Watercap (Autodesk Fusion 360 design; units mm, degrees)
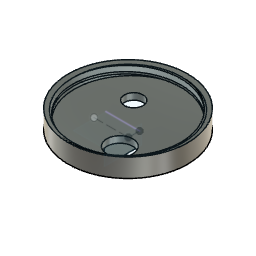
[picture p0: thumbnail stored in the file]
cylinder_primitive "CylinderPrimitive1" Height 10 Diameter 64
shell "Shell1" innerThickness 3.5
thread "Thread1"
hole "Hole1" HoleDepth 30 HoleDiameter 14 TipAngle 118
hole "Hole2" HoleDepth 30 HoleDiameter 10 TipAngle 118
box_primitive "BoxPrimitive1" DistanceX 20 DistanceY 20 DistanceZ 10 OffsetDistanceX 0 OffsetDistanceY 0
move "Move1"
sketch "Sketch5" plane through (0, 0, -9.5813) normal (0, 0, -1) x axis (1, 0, 0)
  line L1 (-18.8277, 13.8567) -> (1.1723, 13.8567)
  line L2 (-18.8277, -6.1433) -> (-18.8277, 13.8567)
  line L3 (1.1723, -6.1433) -> (-18.8277, -6.1433)
  line L4 (1.1723, 13.8567) -> (1.1723, -6.1433)
  line L5 (0.0733, 11.5199) -> (-17.9267, 11.5199)
  line L6 (0.0733, -6.4801) -> (0.0733, 11.5199)
  line L7 (-17.9267, -6.4801) -> (0.0733, -6.4801)
  line L8 (-17.9267, 11.5199) -> (-17.9267, -6.4801)
  point P6 (-17.9267, 11.5199)
  point P7 (0.0733, 11.5199)
  point P9 (-17.9267, -6.4801)
  horizontal L5
  vertical L6
  horizontal L7
  vertical L8
  dimension "d15" distance P6 P7 = 18
  dimension "d16" distance P6 P9 = 18
extrude "Extrude1" cut sketch "Sketch5" profile of L3 L5 L6 L8 against normal blind 6
sketch "Sketch6" plane through (0, 0, -3.5813) normal (0, 0, -1) x axis (1, 0, 0)
  line L1 (-17.9267, -6.1433) -> (-17.9267, 11.5199)
  line L2 (0.0733, 11.5199) -> (0.0733, -6.1433)
  line L3 (-17.9267, 11.5199) -> (0.0733, 11.5199)
  line L4 (-15.9267, -6.1433) -> (-17.9267, -6.1433)
  line L5 (-15.9267, -4.1433) -> (-15.9267, -6.1433)
  line L6 (-17.9267, -4.1433) -> (-15.9267, -4.1433)
  line L7 (-17.9267, -6.1433) -> (-17.9267, -4.1433)
  line L8 (0.0733, -6.1433) -> (-17.9267, -6.1433)
  point P3 (-17.9267, -6.1433)
  point P6 (-17.9267, -6.1433)
  point P7 (-15.9267, -6.1433)
  point P9 (-17.9267, -4.1433)
  horizontal L4
  vertical L5
  horizontal L6
  vertical L7
  coincident P3 P6
  dimension "d19" distance P6 P7 = 2
  dimension "d20" distance P6 P9 = 2
extrude "Extrude2" new body sketch "Sketch6" profile of L1 L4 L5 L6 L7 along normal blind 6
rectangular_pattern "R-Pattern1" uSpaceDistance -16 vSpaceDistance 9
sketch "Sketch7" plane through (1.1723, 0, 0) normal (1, 0, 0) x axis (0, 1, 0)
  line L1 (6.1433, 0.4187) -> (6.1433, -9.5813)
  line L2 (-13.8567, 0.4187) -> (6.1433, 0.4187)
  line L3 (-13.8567, -9.5813) -> (-13.8567, 0.4187)
  line L4 (6.1433, -9.5813) -> (-13.8567, -9.5813)
sketch "Sketch8" plane through (0, 0, -3.5813) normal (0, 0, -1) x axis (1, 0, 0)
  line L1 (-17.9267, -6.1433) -> (-17.9267, 11.5199)
  line L2 (0.0733, 11.5199) -> (0.0733, -6.1433)
  line L3 (-17.9267, 11.5199) -> (0.0733, 11.5199)
  line L4 (0.0733, -0.1433) -> (0.0733, -6.1433)
  line L5 (-18.3663, -0.1433) -> (0.0733, -0.1433)
  line L6 (0.0733, -6.1433) -> (-17.9267, -6.1433)
  point P4 (0.0733, -6.1433)
  point P6 (0.0733, -6.1433)
  point P7 (0.0733, -0.1433)
  coincident P4 P6
  coincident L2 P7
  perpendicular L2 L5
  dimension "d27" distance P6 P7 = 6
hole "Hole3" HoleDepth 5 HoleDiameter 2 TipAngle 118
rectangular_pattern "R-Pattern2" uSpaceDistance 14 vSpaceDistance 0
sketch "Sketch10" plane through (0, 0, -9.5813) normal (0, 0, -1) x axis (1, 0, 0)
  line L1 (-14, 11.2881) -> (-4.8967, 11.2881)
  line L2 (-14, 14) -> (-14, 11.2881)
  line L3 (-4.8967, 14) -> (-14, 14)
  line L4 (-4.8967, 11.2881) -> (-4.8967, 14)
  horizontal L1
  vertical L2
  horizontal L3
  vertical L4
extrude "Extrude3" cut sketch "Sketch10" against normal blind 4
combine "Combine1"
sketch "Sketch12" plane through (0, 0, 10) normal (0, 0, 1) x axis (-1, 0, 0)
  curve K1 (28.9244, 1.8723) -> (-15.6121, 27.0397)
  curve K2 (-27.0397, 15.6121) -> (-1.8723, -28.9244)
  arc A1 centre (0, 0) radius 28.985 clockwise from (28.9244, 1.8723) to (-1.8723, -28.9244)
  arc A2 centre (0, 0) radius 31.2231 clockwise from (-27.0397, 15.6121) to (-15.6121, 27.0397)
  circle C1 centre (0, 0) radius 32
sketch "Sketch13" plane through (0, 0, 10) normal (0, 0, 1) x axis (-1, 0, 0)
sketch "Sketch14" plane through (0, 0, -3.5813) normal (0, 0, -1) x axis (1, 0, 0)
  line L1 (-3.8769, -6.3082) -> (-13.8769, -6.3082)
  line L2 (-3.8769, -2.3082) -> (-3.8769, -6.3082)
  line L3 (-13.8769, -2.3082) -> (-3.8769, -2.3082)
  line L4 (-13.8769, -6.3082) -> (-13.8769, -2.3082)
  point P2 (-13.8769, -6.3082)
  point P3 (-3.8769, -6.3082)
  point P5 (-13.8769, -2.3082)
  horizontal L1
  vertical L2
  horizontal L3
  vertical L4
  dimension "d37" distance P2 P3 = 10
  dimension "d38" distance P2 P5 = 4
extrude "Extrude4" cut sketch "Sketch14" against normal blind 3.5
